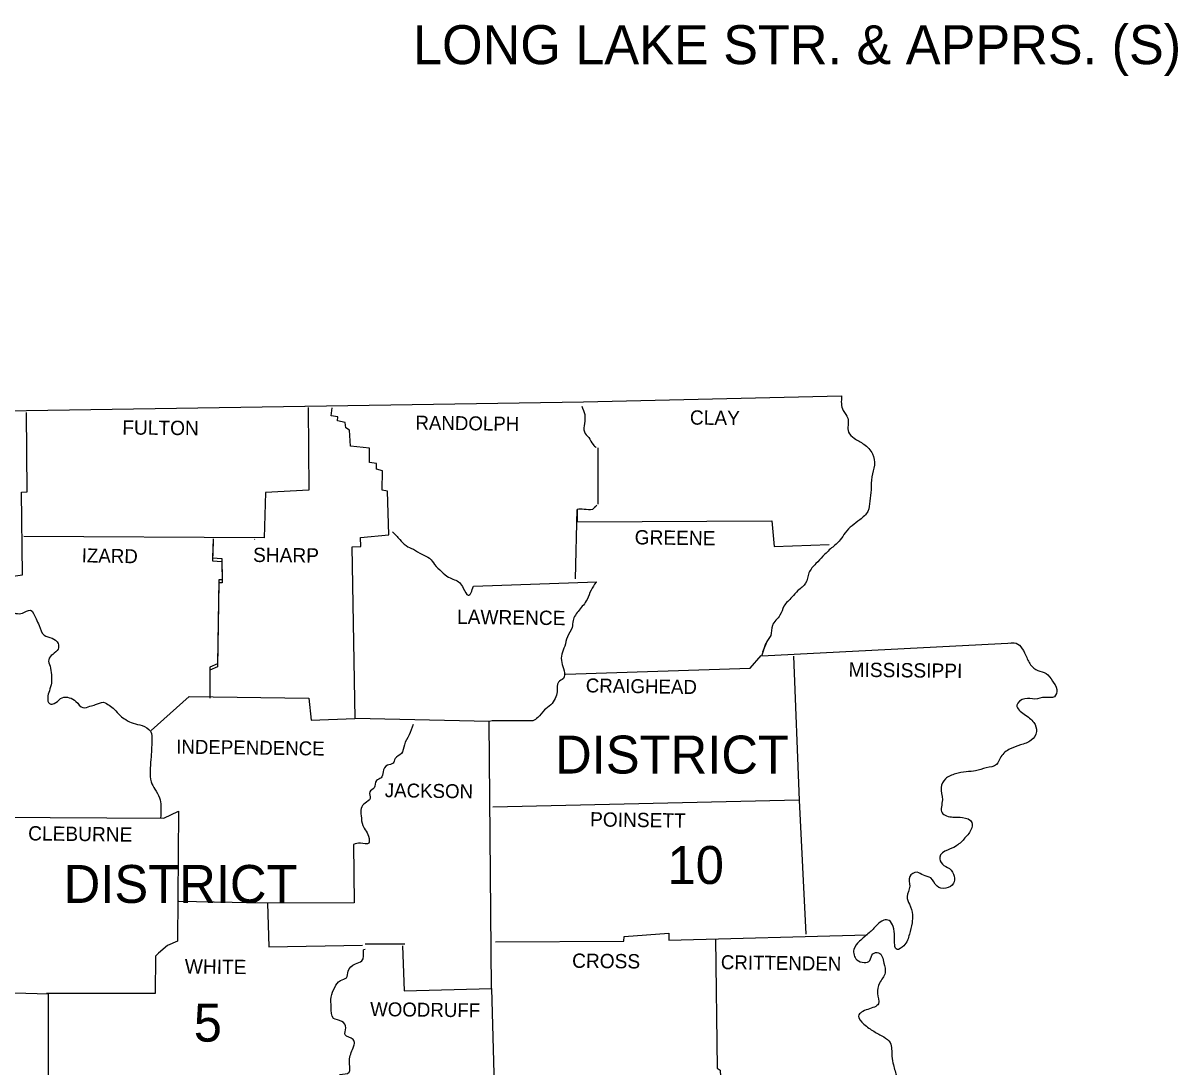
# Model space of a CAD drawing. Extents: x 1373884 to 1376992, y 1168426 to 1170473.
# Drawn here: x 1376598.2 to 1376945.3, y 1170084.3 to 1170398.1 of the extents above; entities that cross this region are included whole.
import ezdxf

# ---------------------------------------------------------------- set-up
doc = ezdxf.new("R2010")
doc.units = 0
doc.layers.add('1', color=7, linetype='Continuous')
doc.layers.add('R_Draft', color=7, linetype='Continuous')

msp = doc.modelspace()

# ---------------------------------------------------------------- linework, layer by layer
at = {"layer": 'R_Draft'}
for p, q in [((1376820.19, 1170207.9), (1376821.39, 1170211.6)), ((1376820.49, 1170209.1), (1376821.69, 1170212)), ((1376700.99, 1170121.3), (1376712.89, 1170121.3))]:
    msp.add_line(p, q, dxfattribs=at)
for points in [[(1376295.59, 1170281.4), (1376457.29, 1170281.3), (1376599.19, 1170281.6), (1376766.59, 1170284.2), (1376844.19, 1170286)], [(1376568.89, 1170039.7), (1376591.39, 1170039.8), (1376592.39, 1170051.6), (1376605.79, 1170052.6), (1376605.79, 1170106.2), (1376588.79, 1170106.7), (1376589.09, 1170159.4), (1376567.69, 1170160.8), (1376567.39, 1170184.4), (1376566.69, 1170185.6), (1376567.29, 1170200.4), (1376579.69, 1170200.8), (1376580.19, 1170213), (1376593.79, 1170213.5), (1376593.99, 1170221.4), (1376591.59, 1170224.5), (1376590.99, 1170231.2), (1376597.99, 1170232.2), (1376597.69, 1170257.1), (1376599.39, 1170257.2), (1376599.19, 1170281)], [(1376683.89, 1170282.5), (1376684.09, 1170257.7), (1376671.09, 1170257), (1376670.69, 1170243.4), (1376598.39, 1170243.8)], [(1376712.19, 1170120.7), (1376712.69, 1170107.2), (1376738.99, 1170107.9), (1376738.29, 1170188.1), (1376697.99, 1170189), (1376697.09, 1170240.6), (1376699.69, 1170240.7), (1376699.59, 1170243.5), (1376708.09, 1170244.3), (1376707.69, 1170257.4), (1376706.09, 1170257.7), (1376706.19, 1170263.5), (1376704.39, 1170264), (1376704.39, 1170265.7), (1376702.29, 1170266), (1376702.29, 1170270.3), (1376696.59, 1170270.9), (1376696.29, 1170275.7), (1376695.19, 1170276.4), (1376694.99, 1170278), (1376692.69, 1170278.5), (1376692.79, 1170279.7), (1376690.79, 1170280), (1376691.09, 1170282.4)], [(1376770.99, 1170270.4), (1376770.99, 1170253.5)], [(1376764.19, 1170231), (1376764.69, 1170251.9), (1376764.69, 1170248.2), (1376823.19, 1170248.5), (1376823.99, 1170240.7), (1376840.49, 1170241.3)], [(1376655.29, 1170243.1), (1376655.09, 1170237.3), (1376657.89, 1170237.1), (1376657.99, 1170230.7), (1376656.99, 1170230.7), (1376656.59, 1170205.5), (1376654.29, 1170204.5), (1376654.29, 1170196.1)], [(1376655.29, 1170242.2), (1376655.09, 1170236.4), (1376657.89, 1170236.2), (1376657.99, 1170229.8), (1376656.99, 1170229.8), (1376656.59, 1170204.6), (1376654.29, 1170203.6), (1376654.29, 1170195.2)], [(1376667.79, 1170242.9), (1376667.89, 1170243)], [(1376733.59, 1170228.8), (1376770.69, 1170230.1)], [(1376820.19, 1170207.9), (1376896.09, 1170211.8)], [(1376761.19, 1170202.4), (1376816.69, 1170204.2), (1376819.99, 1170208)], [(1376829.79, 1170207.8), (1376831.49, 1170164.5), (1376833.49, 1170124.2)], [(1376636.69, 1170185.4), (1376648.09, 1170195.7), (1376684.09, 1170195.2), (1376684.79, 1170188.5), (1376697.89, 1170189)], [(1376751.39, 1170188.3), (1376739.19, 1170188.3), (1376738.29, 1170188.1)], [(1376831.49, 1170164.5), (1376739.39, 1170162.4)], [(1376589.09, 1170159.4), (1376640.49, 1170159.1), (1376644.89, 1170161.2), (1376644.59, 1170122.1), (1376641.59, 1170120.8), (1376638.89, 1170118.5), (1376637.99, 1170117.6), (1376637.89, 1170106.4), (1376605.19, 1170106.4)], [(1376697.49, 1170151.2), (1376697.69, 1170133.6), (1376671.69, 1170133.5), (1376644.99, 1170134)], [(1376671.69, 1170133.5), (1376672.09, 1170120.4), (1376700.19, 1170120.9)], [(1376740.19, 1170121.9), (1376778.79, 1170122.1), (1376778.89, 1170123.5), (1376792.29, 1170124.5), (1376792.29, 1170122.4), (1376851.86, 1170124.04)], [(1376806.29, 1170122.79), (1376806.79, 1170083.9), (1376807.69, 1170083.3), (1376808.01, 1170077.77)], [(1376700.99, 1170119.6), (1376700.49, 1170119.5)], [(1376738.99, 1170107.9), (1376740.49, 1170053.1), (1376716.69, 1170053), (1376716.59, 1170050.8), (1376709.69, 1170050.4), (1376709.09, 1170039), (1376700.69, 1170039)]]:
    msp.add_lwpolyline(points, dxfattribs=at)
for points in [[(1376844.19, 1170286), (1376844.69, 1170281.6), (1376846.09, 1170279.3), (1376846.29, 1170275.1), (1376847.99, 1170273.3), (1376850.89, 1170271.5), (1376853.49, 1170268.6), (1376854.09, 1170265.2), (1376853.29, 1170261.7), (1376853.09, 1170257.8), (1376852.69, 1170254.4), (1376852.09, 1170251.3), (1376849.69, 1170248.8), (1376847.39, 1170247), (1376845.29, 1170244.9), (1376843.79, 1170242.7), (1376841.19, 1170240.3), (1376838.59, 1170237.8), (1376836.49, 1170235.6), (1376834.39, 1170232.8), (1376833.39, 1170229.7), (1376831.09, 1170227.5), (1376829.29, 1170225.5), (1376826.89, 1170222.8), (1376825.69, 1170220.1), (1376823.39, 1170217), (1376822.89, 1170214), (1376821.39, 1170211.6), (1376821.29, 1170211.2)], [(1376844.19, 1170286), (1376844.69, 1170281.6), (1376846.09, 1170279.3), (1376846.29, 1170275.1), (1376847.99, 1170273.3), (1376850.89, 1170271.5), (1376853.49, 1170268.6), (1376854.09, 1170265.2), (1376853.29, 1170261.7), (1376853.09, 1170257.8), (1376852.69, 1170254.4), (1376852.09, 1170251.3), (1376849.69, 1170248.8), (1376847.39, 1170247), (1376845.29, 1170244.9), (1376843.79, 1170242.7), (1376841.19, 1170240.3), (1376838.59, 1170237.8), (1376836.49, 1170235.6), (1376834.39, 1170232.8), (1376833.39, 1170229.7), (1376831.09, 1170227.5), (1376829.29, 1170225.5), (1376826.89, 1170222.8), (1376825.69, 1170220.1), (1376823.39, 1170217), (1376822.89, 1170214), (1376821.39, 1170211.6), (1376821.29, 1170211.2)], [(1376766.09, 1170282.9), (1376766.99, 1170280.4), (1376766.89, 1170277.7), (1376766.89, 1170275.2), (1376768.19, 1170273.5), (1376769.49, 1170271.4), (1376770.49, 1170270.5)], [(1376770.59, 1170253.2), (1376769.29, 1170251.9), (1376766.79, 1170251.9), (1376764.69, 1170251.9)], [(1376709.19, 1170245.2), (1376711.39, 1170242.9), (1376713.29, 1170241), (1376715.49, 1170239.9), (1376718.09, 1170238.4), (1376720.39, 1170237.2), (1376721.89, 1170235.3), (1376723.99, 1170233.2), (1376726.09, 1170231.5), (1376729.39, 1170229.9), (1376730.49, 1170228.2), (1376731.99, 1170226.1), (1376733.59, 1170228.8)], [(1376770.39, 1170230), (1376768.89, 1170227.6), (1376767.69, 1170224.8), (1376765.29, 1170221.6), (1376763.49, 1170218.5), (1376763.19, 1170216.4), (1376761.79, 1170213.6), (1376760.99, 1170210.8), (1376760.09, 1170208.4), (1376760.09, 1170205.9), (1376760.79, 1170203.4), (1376760.59, 1170201.1), (1376759.09, 1170200), (1376758.69, 1170197.1), (1376758.09, 1170195.1), (1376756.79, 1170193.1), (1376754.89, 1170191.6), (1376752.89, 1170189.3), (1376751.39, 1170188.3)], [(1376593.99, 1170221.4), (1376597.99, 1170220.7), (1376600.39, 1170221.6), (1376602.09, 1170219), (1376602.99, 1170217), (1376604.49, 1170214.1), (1376606.89, 1170213.2), (1376608.69, 1170211.6), (1376608.69, 1170209.9), (1376607.09, 1170208.3), (1376605.89, 1170206.7), (1376606.29, 1170204.8), (1376606.69, 1170202.2), (1376606.69, 1170199.7), (1376606.09, 1170197.4), (1376605.59, 1170195.3), (1376606.09, 1170193.5), (1376607.99, 1170193.8), (1376609.99, 1170195.3), (1376612.09, 1170195.3), (1376614.09, 1170194.2), (1376616.19, 1170192.3), (1376618.29, 1170192.7), (1376619.99, 1170193.2), (1376622.39, 1170193.9), (1376624.09, 1170193), (1376625.59, 1170191.8), (1376627.39, 1170189.9), (1376629.09, 1170188.7), (1376631.29, 1170187.6), (1376633.99, 1170186.9), (1376636.49, 1170185.2), (1376636.89, 1170182.3), (1376636.79, 1170179.8), (1376636.59, 1170176.7), (1376636.39, 1170173.3), (1376636.69, 1170170), (1376637.79, 1170167.8), (1376639.19, 1170165.2), (1376639.59, 1170162.8), (1376639.49, 1170159)], [(1376894.99, 1170211.7), (1376896.09, 1170211.8), (1376899.49, 1170208.2), (1376900.99, 1170205.2), (1376903.19, 1170203.5), (1376905.69, 1170202.6), (1376907.59, 1170200.3), (1376908.89, 1170197.8), (1376908.19, 1170195.6), (1376905.39, 1170195.4), (1376902.29, 1170194.9), (1376899.29, 1170195), (1376896.89, 1170193), (1376899.09, 1170190.3), (1376901.99, 1170187.8), (1376902.79, 1170185.1), (1376901.19, 1170182.5), (1376897.99, 1170181.1), (1376894.89, 1170179.9), (1376892.09, 1170177.5), (1376890.79, 1170175.2), (1376887.69, 1170174.2), (1376884.49, 1170173.3), (1376881.69, 1170173), (1376878.49, 1170172.4), (1376875.39, 1170170.9), (1376874.09, 1170168.3), (1376874.49, 1170164.6), (1376874.39, 1170160.7), (1376877.69, 1170159.4), (1376880.59, 1170159.3), (1376883.39, 1170157.8), (1376883.09, 1170155.6), (1376880.99, 1170152.8), (1376878.49, 1170150.6), (1376875.99, 1170149.5), (1376873.69, 1170147.4), (1376874.49, 1170145.3), (1376876.59, 1170143.9), (1376878.09, 1170141.6), (1376877.89, 1170139.5), (1376875.49, 1170138), (1376872.89, 1170138.6), (1376870.99, 1170141.1), (1376868.79, 1170141.9), (1376866.89, 1170142.8), (1376864.69, 1170141.5), (1376864.69, 1170138.6), (1376863.89, 1170135.5), (1376864.59, 1170133.2), (1376865.49, 1170130), (1376865.39, 1170127.6), (1376864.59, 1170124.2), (1376862.89, 1170120.7), (1376860.89, 1170119.6), (1376860.09, 1170123.4), (1376859.69, 1170126.5), (1376858.49, 1170128.3), (1376856.89, 1170128.4), (1376854.79, 1170126.9), (1376852.49, 1170124.6), (1376849.59, 1170122.1), (1376847.89, 1170119.6), (1376848.79, 1170116.5), (1376850.99, 1170115.7), (1376852.69, 1170116.3), (1376853.59, 1170118.3), (1376855.29, 1170118.6), (1376856.89, 1170115.5)], [(1376894.99, 1170211.7), (1376896.09, 1170211.8), (1376899.49, 1170208.2), (1376900.99, 1170205.2), (1376903.19, 1170203.5), (1376905.69, 1170202.6), (1376907.59, 1170200.3), (1376908.89, 1170197.8), (1376908.19, 1170195.6), (1376905.39, 1170195.4), (1376902.29, 1170194.9), (1376899.29, 1170195), (1376896.89, 1170193), (1376899.09, 1170190.3), (1376901.99, 1170187.8), (1376902.79, 1170185.1), (1376901.19, 1170182.5), (1376897.99, 1170181.1), (1376894.89, 1170179.9), (1376892.09, 1170177.5), (1376890.79, 1170175.2), (1376887.69, 1170174.2), (1376884.49, 1170173.3), (1376881.69, 1170173), (1376878.49, 1170172.4), (1376875.39, 1170170.9), (1376874.09, 1170168.3), (1376874.49, 1170164.6), (1376874.39, 1170160.7), (1376877.69, 1170159.4), (1376880.59, 1170159.3), (1376883.39, 1170157.8), (1376883.09, 1170155.6), (1376880.99, 1170152.8), (1376878.49, 1170150.6), (1376875.99, 1170149.5), (1376873.69, 1170147.4), (1376874.49, 1170145.3), (1376876.59, 1170143.9), (1376878.09, 1170141.6), (1376877.89, 1170139.5), (1376875.49, 1170138), (1376872.89, 1170138.6), (1376870.99, 1170141.1), (1376868.79, 1170141.9), (1376866.89, 1170142.8), (1376864.69, 1170141.5), (1376864.69, 1170138.6), (1376863.89, 1170135.5), (1376864.59, 1170133.2), (1376865.49, 1170130), (1376865.39, 1170127.6), (1376864.59, 1170124.2), (1376862.89, 1170120.7), (1376860.89, 1170119.6), (1376860.09, 1170123.4), (1376859.69, 1170126.5), (1376858.49, 1170128.3), (1376856.89, 1170128.4), (1376854.79, 1170126.9), (1376852.49, 1170124.6), (1376849.59, 1170122.1), (1376847.89, 1170119.6), (1376848.79, 1170116.5), (1376850.99, 1170115.7), (1376852.69, 1170116.3), (1376853.59, 1170118.3), (1376855.29, 1170118.6), (1376856.89, 1170115.5)], [(1376715.39, 1170187.2), (1376714.19, 1170184.1), (1376712.79, 1170181.1), (1376711.89, 1170178.5), (1376709.99, 1170177), (1376709.39, 1170175.6), (1376707.69, 1170175), (1376706.39, 1170173), (1376705.79, 1170171.2), (1376704.39, 1170170.4), (1376703.69, 1170168.2), (1376702.39, 1170167), (1376702.49, 1170165), (1376700.99, 1170163.6), (1376699.79, 1170162), (1376699.79, 1170159.8), (1376700.29, 1170156.9), (1376701.29, 1170155.2), (1376702.19, 1170153), (1376702.09, 1170151.6), (1376699.59, 1170151.6), (1376697.49, 1170151.2)], [(1376688.29, 1170059.8), (1376687.79, 1170060.5), (1376688.39, 1170062.7), (1376688.69, 1170064.1), (1376687.69, 1170066.1), (1376688.59, 1170067.8), (1376689.59, 1170069.6), (1376689.89, 1170071.7), (1376690.69, 1170073.1), (1376690.39, 1170074.9), (1376690.79, 1170077.4), (1376691.89, 1170079.3), (1376693.49, 1170082), (1376696.19, 1170082.7), (1376696.39, 1170083.8), (1376696.29, 1170086.3), (1376697.39, 1170090), (1376697.79, 1170091.3), (1376697.39, 1170092.5), (1376694.99, 1170093.9), (1376695.19, 1170096), (1376693.99, 1170098), (1376691.49, 1170098.9), (1376690.79, 1170102.3), (1376690.79, 1170105.3), (1376691.89, 1170108.2), (1376693.59, 1170110.3), (1376695.39, 1170111.1), (1376695.89, 1170113.1), (1376698.09, 1170115.3), (1376699.99, 1170116.2), (1376700.49, 1170119.5)], [(1376856.89, 1170115.5), (1376857.29, 1170112.6), (1376855.59, 1170109.5), (1376854.99, 1170106.4), (1376855.29, 1170103.3), (1376852.09, 1170101.6), (1376849.29, 1170099.6), (1376850.89, 1170097.2), (1376853.89, 1170095), (1376856.89, 1170093.3), (1376858.79, 1170091.6), (1376859.29, 1170087.5), (1376859.79, 1170084.9), (1376860.79, 1170081.3), (1376861.19, 1170078.8), (1376859.39, 1170075.8), (1376857.29, 1170075.2), (1376855.09, 1170075.9), (1376852.49, 1170076.1), (1376850.39, 1170074.1), (1376848.89, 1170071.3), (1376847.39, 1170068.5), (1376846.29, 1170066.1), (1376845.19, 1170063.5), (1376842.99, 1170060.5), (1376840.29, 1170060), (1376837.09, 1170059.2), (1376835.19, 1170057), (1376835.49, 1170053.3), (1376837.29, 1170050.8), (1376838.69, 1170047.7), (1376839.69, 1170045), (1376839.19, 1170041.6), (1376837.79, 1170039.1), (1376835.99, 1170037.6), (1376835.19, 1170034.4), (1376833.89, 1170032), (1376832.69, 1170031.2), (1376830.29, 1170031.4), (1376827.69, 1170031.9), (1376825.49, 1170031.7), (1376823.39, 1170030.6), (1376821.29, 1170031.3), (1376819.09, 1170033.7), (1376817.29, 1170035.5), (1376815.29, 1170036.2), (1376813.19, 1170035.1), (1376812.79, 1170031.8), (1376813.79, 1170028.4), (1376814.69, 1170023.8), (1376813.79, 1170021), (1376813.49, 1170016.4)], [(1376856.89, 1170115.5), (1376857.29, 1170112.6), (1376855.59, 1170109.5), (1376854.99, 1170106.4), (1376855.29, 1170103.3), (1376852.09, 1170101.6), (1376849.29, 1170099.6), (1376850.89, 1170097.2), (1376853.89, 1170095), (1376856.89, 1170093.3), (1376858.79, 1170091.6), (1376859.29, 1170087.5), (1376859.79, 1170084.9), (1376860.79, 1170081.3), (1376861.19, 1170078.8), (1376859.39, 1170075.8), (1376857.29, 1170075.2), (1376855.09, 1170075.9), (1376852.49, 1170076.1), (1376850.39, 1170074.1), (1376848.89, 1170071.3), (1376847.39, 1170068.5), (1376846.29, 1170066.1), (1376845.19, 1170063.5), (1376842.99, 1170060.5), (1376840.29, 1170060), (1376837.09, 1170059.2), (1376835.19, 1170057), (1376835.49, 1170053.3), (1376837.29, 1170050.8), (1376838.69, 1170047.7), (1376839.69, 1170045), (1376839.19, 1170041.6), (1376837.79, 1170039.1), (1376835.99, 1170037.6), (1376835.19, 1170034.4), (1376833.89, 1170032), (1376832.69, 1170031.2), (1376830.29, 1170031.4), (1376827.69, 1170031.9), (1376825.49, 1170031.7), (1376823.39, 1170030.6), (1376821.29, 1170031.3), (1376819.09, 1170033.7), (1376817.29, 1170035.5), (1376815.29, 1170036.2), (1376813.19, 1170035.1), (1376812.79, 1170031.8), (1376813.79, 1170028.4), (1376814.69, 1170023.8), (1376813.79, 1170021), (1376813.49, 1170016.4)]]:
    msp.add_spline(points, degree=3, dxfattribs=at)

# ---------------------------------------------------------------- texts
at = {"layer": '1'}
msp.add_text('LONG LAKE STR. & APPRS. (S)', height=11.724, dxfattribs=at).set_placement((1376715.39, 1170385.74))
at = {"layer": 'R_Draft'}
for s, height, rotation, p in [('CLAY', 4.3, 359.2258, (1376798.59, 1170277.4)), ('FULTON', 4.3, 359.4996, (1376627.99, 1170274.4)), ('RANDOLPH', 4.201, 359.2583, (1376716.09, 1170275.9)), ('GREENE', 4.301, 359.2361, (1376781.99, 1170241.4)), ('IZARD', 4.199, 358.9258, (1376615.79, 1170236)), ('SHARP', 4.3, 359.3905, (1376667.29, 1170236.1)), ('LAWRENCE', 4.301, 359.2678, (1376728.59, 1170217.5)), ('MISSISSIPPI', 4.2996, 359.3097, (1376846.29, 1170201.6)), ('CRAIGHEAD', 4.201, 359.1159, (1376767.29, 1170196.9)), ('INDEPENDENCE', 4.1994, 359.2187, (1376644.19, 1170178.5)), ('JACKSON', 4.199, 359.1352, (1376706.89, 1170165.4)), ('POINSETT', 4.3, 359.1987, (1376768.59, 1170156.6)), ('CLEBURNE', 4.3, 359.2535, (1376599.69, 1170152.4)), ('CROSS', 4.3, 359.3839, (1376763.19, 1170114.1)), ('CRITTENDEN', 4.201, 359.213, (1376807.89, 1170113.7)), ('WHITE', 4.301, 359.3139, (1376646.79, 1170112.4)), ('WOODRUFF', 4.199, 359.2748, (1376702.49, 1170099.6))]:
    msp.add_text(s, height=height, rotation=rotation, dxfattribs=at).set_placement(p)
for s, p in [('DISTRICT', (1376758.09, 1170172.5)), ('10', (1376791.89, 1170139.3)), ('DISTRICT', (1376610.39, 1170133.6)), ('5', (1376649.49, 1170091.9))]:
    msp.add_text(s, height=11.4, dxfattribs=at).set_placement(p)

doc.saveas('drawing.dxf')
